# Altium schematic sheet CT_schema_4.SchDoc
size 479 x 328 mm
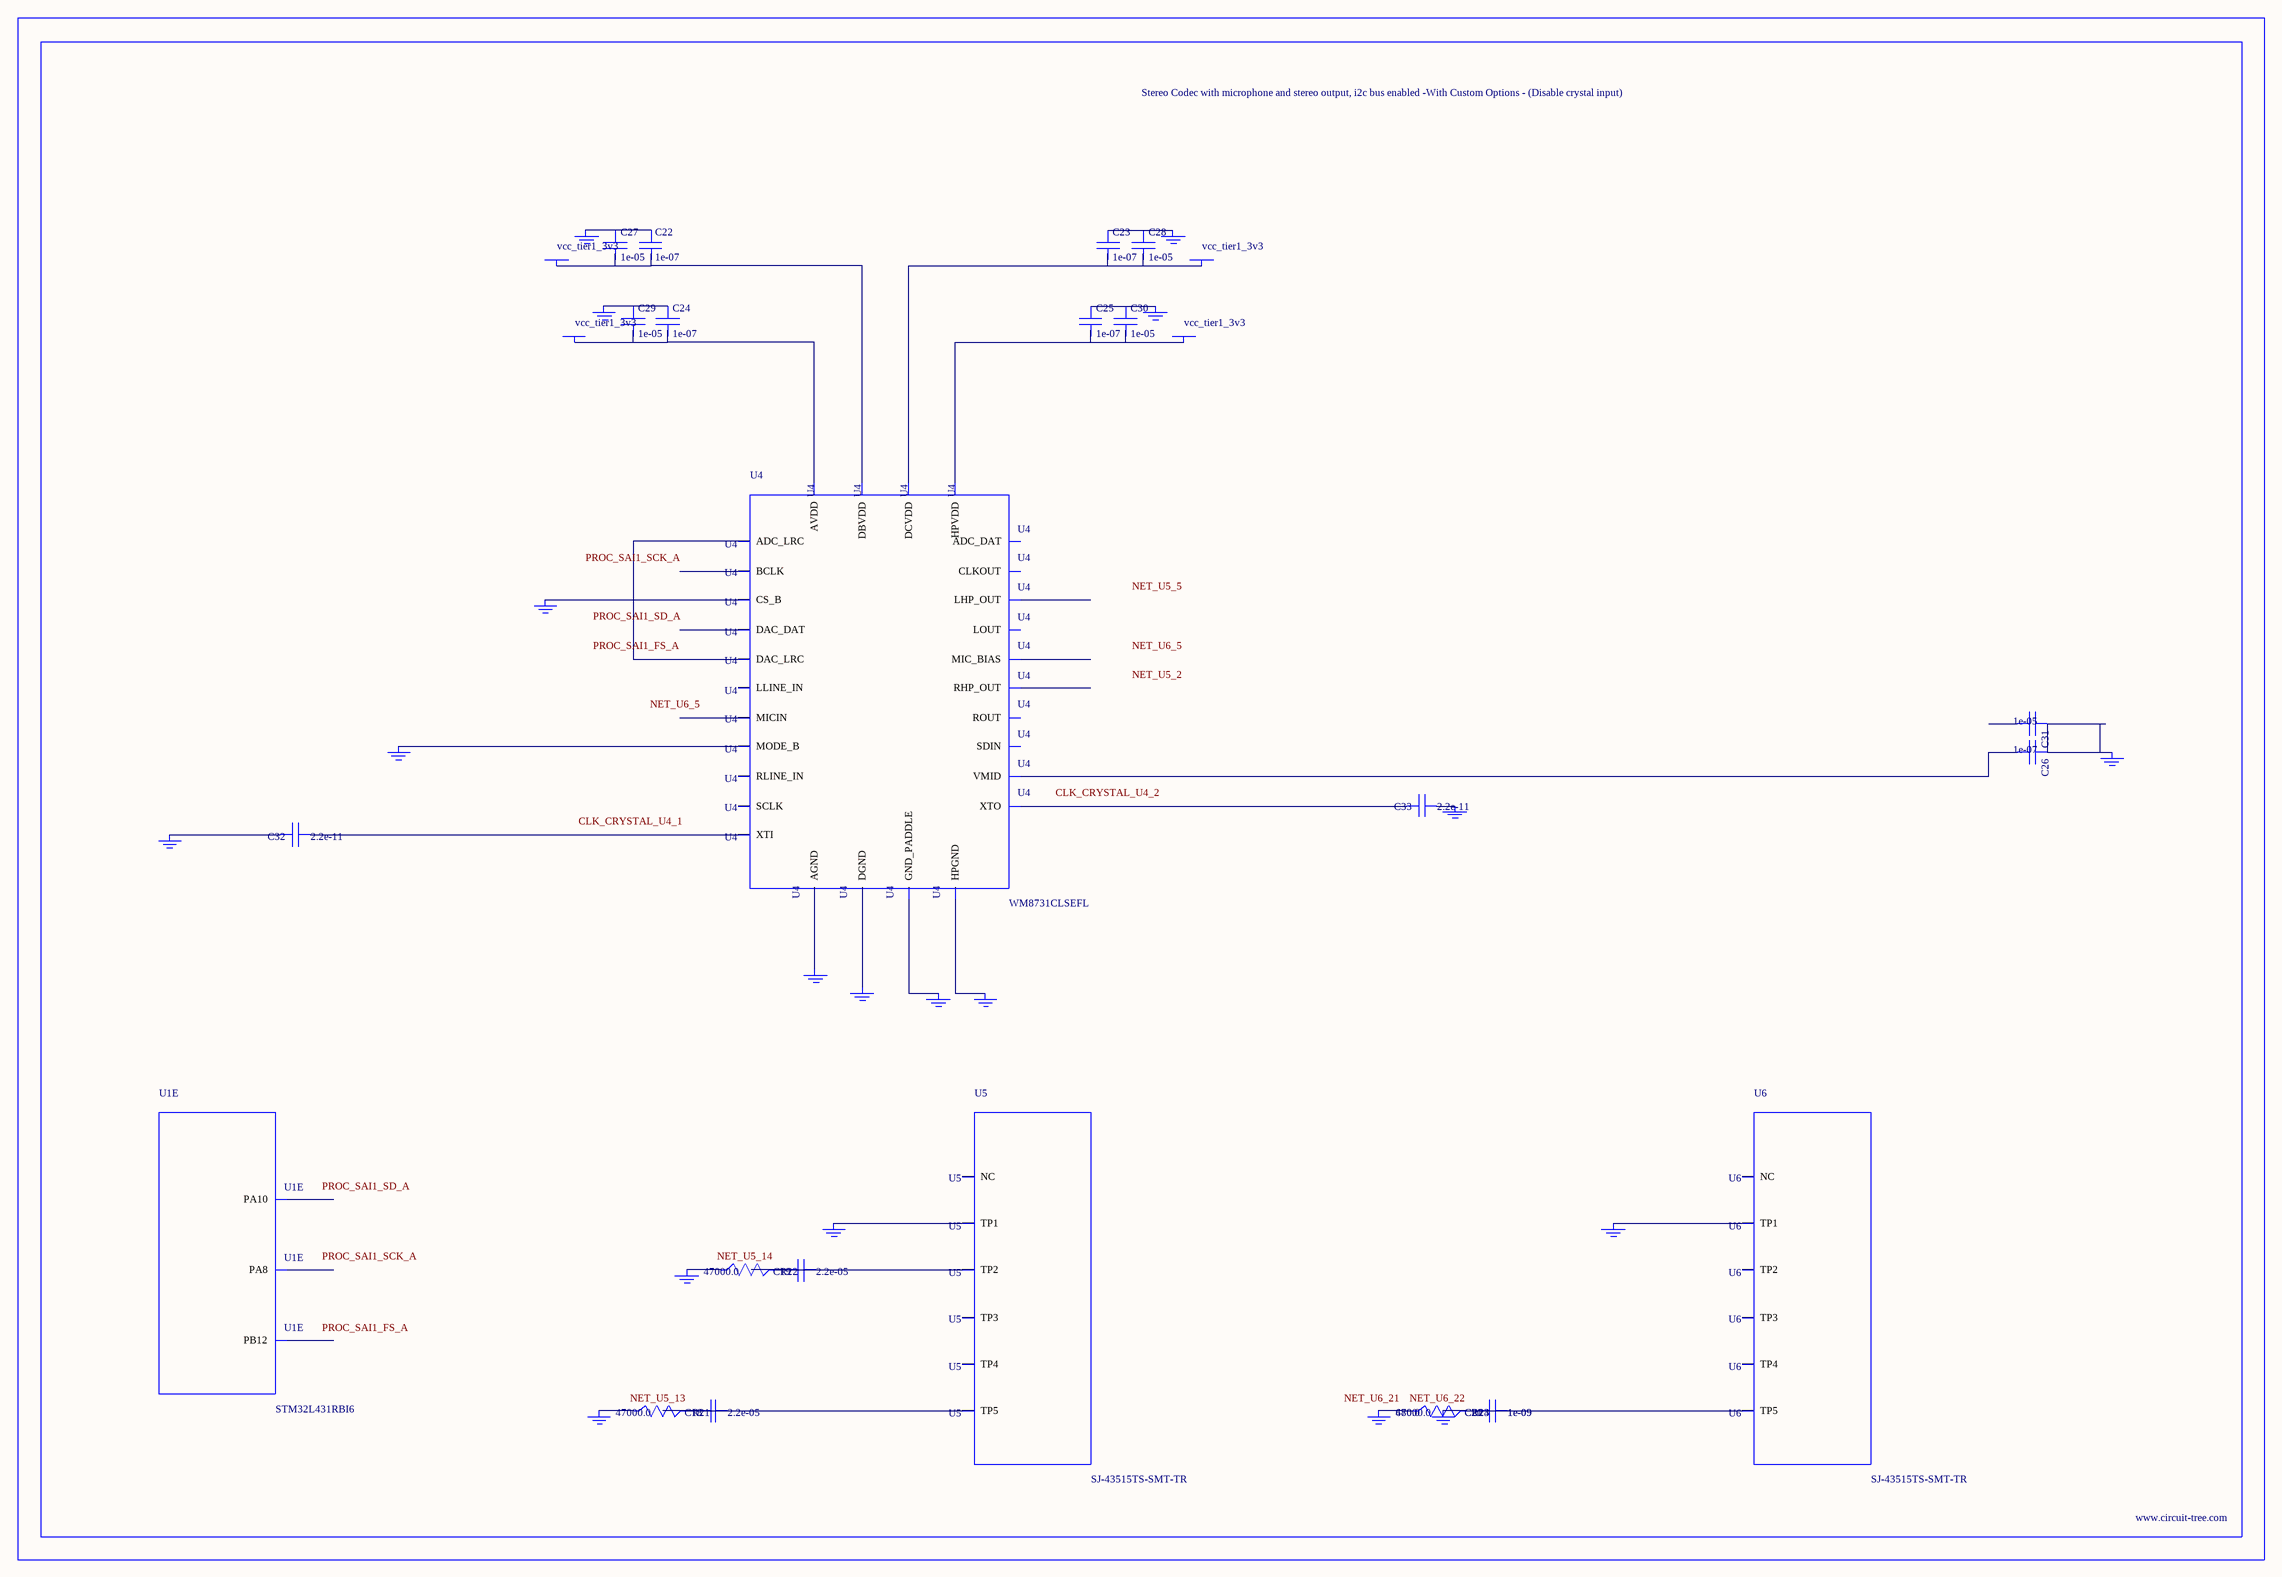
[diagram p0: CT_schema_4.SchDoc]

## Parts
BORDER3  (no value)
C18  2.2e-05  [C1210]
C19  2.2e-05  [C1210]
C20  1e-09  [C0402]
C21  1e-09  [C0402]
C22  1e-07  [C0402]
C23  1e-07  [C0402]
C24  1e-07  [C0402]
C25  1e-07  [C0402]
C26  1e-07  [C0402]
C27  1e-05  [C0805]
C28  1e-05  [C0805]
C29  1e-05  [C0805]
C30  1e-05  [C0805]
C31  1e-05  [C0805]
C32  2.2e-11  [C0402]
C33  2.2e-11  [C0402]
GND_INSTANCE_3_0  (no value)
GND_INSTANCE_3_1  (no value)
GND_INSTANCE_3_2  (no value)
GND_INSTANCE_3_3  (no value)
GND_INSTANCE_3_4  (no value)
GND_INSTANCE_3_5  (no value)
GND_INSTANCE_3_6  (no value)
GND_INSTANCE_3_7  (no value)
GND_INSTANCE_3_8  (no value)
GND_INSTANCE_3_9  (no value)
GND_INSTANCE_3_10  (no value)
GND_INSTANCE_3_11  (no value)
GND_INSTANCE_3_12  (no value)
GND_INSTANCE_3_13  (no value)
GND_INSTANCE_3_14  (no value)
GND_INSTANCE_3_15  (no value)
GND_INSTANCE_3_16  (no value)
GND_INSTANCE_3_17  (no value)
GND_INSTANCE_3_18  (no value)
POWER_INSTANCE_3_0  vcc_tier1_3v3
POWER_INSTANCE_3_1  vcc_tier1_3v3
POWER_INSTANCE_3_2  vcc_tier1_3v3
POWER_INSTANCE_3_3  vcc_tier1_3v3
R21  47000.0  [R0603]
R22  47000.0  [R0603]
R23  47000.0  [R0603]
R24  680.0  [R0603]
U1  STM32L431RBI6  [UFBGA64]  (part E of 6)
U4  WM8731CLSEFL  [QFN-28]
U5  SJ-43515TS-SMT-TR  [SJ-43515TS-SMT-TR]
U6  SJ-43515TS-SMT-TR  [SJ-43515TS-SMT-TR]

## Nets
NetC18_1: C18.1 C18.2 R21.2 U5.5(TP5)
NetC19_1: C19.1 C19.2 R22.2 U5.2(TP2)
NetC20_1: C20.1 C20.2 C21.1 C21.2 GND_INSTANCE_3_18.0(GND) R23.2 R24.2 U6.5(TP5)
NetC22_1: C22.1 C27.1 GND_INSTANCE_3_3.0(GND)
NetC22_2: C22.2 C27.2 POWER_INSTANCE_3_1.0(PWR) U4.5(DBVDD)
NetC23_1: C23.1 C28.1 GND_INSTANCE_3_2.0(GND)
NetC23_2: C23.2 C28.2 POWER_INSTANCE_3_0.0(PWR) U4.3(DCVDD)
NetC24_1: C24.1 C29.1 GND_INSTANCE_3_6.0(GND)
NetC24_2: C24.2 C29.2 POWER_INSTANCE_3_3.0(PWR) U4.18(AVDD)
NetC25_1: C25.1 C30.1 GND_INSTANCE_3_4.0(GND)
NetC25_2: C25.2 C30.2 POWER_INSTANCE_3_2.0(PWR) U4.12(HPVDD)
NetC26_1: C26.1 C31.1 GND_INSTANCE_3_7.0(GND)
NetC26_2: C26.2 U4.20(VMID)
NetC32_1: C32.1 U4.1(XTI)
NetC32_2: C32.2 GND_INSTANCE_3_0.0(GND)
NetC33_1: C33.1 GND_INSTANCE_3_1.0(GND)
NetC33_2: C33.2 U4.2(XTO)
NetGND_INSTANCE_3_5_0: GND_INSTANCE_3_5.0(GND) U4.15(HPGND)
NetGND_INSTANCE_3_8_0: GND_INSTANCE_3_8.0(GND) U4.25(MODE_B)
NetGND_INSTANCE_3_9_0: GND_INSTANCE_3_9.0(GND) U4.26(CS_B)
NetGND_INSTANCE_3_10_0: GND_INSTANCE_3_10.0(GND) U4.29(GND_PADDLE)
NetGND_INSTANCE_3_11_0: GND_INSTANCE_3_11.0(GND) U4.4(DGND)
NetGND_INSTANCE_3_12_0: GND_INSTANCE_3_12.0(GND) U4.19(AGND)
NetGND_INSTANCE_3_13_0: GND_INSTANCE_3_13.0(GND) U5.1(TP1)
NetGND_INSTANCE_3_14_0: GND_INSTANCE_3_14.0(GND) R22.1
NetGND_INSTANCE_3_15_0: GND_INSTANCE_3_15.0(GND) R21.1
NetGND_INSTANCE_3_16_0: GND_INSTANCE_3_16.0(GND) U6.1(TP1)
NetGND_INSTANCE_3_17_0: GND_INSTANCE_3_17.0(GND) R23.1 R24.1
NetU4_9: U4.9(DAC_LRC) U4.11(ADC_LRC)

Not connected (* = marked no-connect by the designer): C31 2; U1 C6(PA10) D7(PA8) H8(PB12); U4 6(CLKOUT) 7(BCLK) 8(DAC_DAT) 10(ADC_DAT) 13(LHP_OUT) 14(RHP_OUT) 16(LOUT) 17(ROUT) 21(MIC_BIAS) 22(MICIN) 23(RLINE_IN) 24(LLINE_IN) 27(SDIN) 28(SCLK); U5 3(TP3) 4(TP4) 6(NC); U6 2(TP2) 3(TP3) 4(TP4) 6(NC)

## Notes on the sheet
- Labels drawn without touching a wire or pin: CLK_CRYSTAL_U4_1, CLK_CRYSTAL_U4_2, NET_U5_2, NET_U5_5, NET_U5_13, NET_U5_14, NET_U6_5, NET_U6_21, NET_U6_22, PROC_SAI1_FS_A, PROC_SAI1_SCK_A, PROC_SAI1_SD_A

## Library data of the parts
BORDER3 = BORDER_PAGE3
C18 C19 = C1210C224K5RACTU
C20 C21 = C0402C102K3RAC
C22-C26 = C0402C104K3RACTU
C27-C31 = C0805C106K8RACTU
C32 C33 = C0402C220K3RAC
GND_INSTANCE_3_0-GND_INSTANCE_3_18 = GND
POWER_INSTANCE_3_0-POWER_INSTANCE_3_3 = PWR
R21-R23 = RC0603JR-0747KL
R24 = RC0603JR-07680RL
